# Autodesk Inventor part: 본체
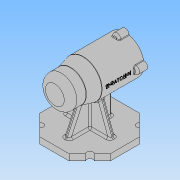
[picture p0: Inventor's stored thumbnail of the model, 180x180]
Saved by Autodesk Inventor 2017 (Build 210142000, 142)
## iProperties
Part Number: 본체
Material: 일반
Document SubType Name: Modeling
Designer: user
Density: 1 g/cm^3
Appearance: 기본값
Author: user
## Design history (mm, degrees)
sketch "스케치1"
  geometry: L1 (-56, 0)-(56, 0); L2 (-56, 0)-(-56, 25); L3 (-56, 25)-(-31, 25); L4 (-31, 25)-(-11, 30); L5 (-11, 30)-(56, 30); L6 (56, 30)-(56, 0); 2 further points
  constraints: 12 end point, 2 perpendicular, 1 coincident, 1 horizontal, 1 midpoint, 1 parallel, 1 vertical
  dimensions: "d0" = 112 distance of L1.start L1.end; "d1" = 25 distance of L2.end L3.end; "d2" = 45 distance from line of L4.end L2; "d3" = 50 diameter of L3 L1; "d4" = 60 diameter of L5 L1
revolve "회전1" sketch "스케치1" stored, may be unused: angle "d5" = 90 deg
sketch "스케치2"
  geometry: L1 (56, -30)-(56, 30) reference; L2 (-50, 0)-(56, 0); L3 (56, 0)-(56, 21); L4 (56, 21)-(41, 21); L5 (41, 21)-(41, 21); L6 (38, 24)-(-10, 24); L7 (-13, 21)-(-13, 21); L8 (-13, 21)-(-24.7, 21); L9 (-25, 20.7)-(-25, 17.5); L10 (-25, 17.5)-(-42.7, 17.5); L11 (-43, 17.2)-(-43, 16); L12 (-43, 16)-(-46.7, 16); L13 (-47, 15.7)-(-47, 10.5); L14 (-47, 10.5)-(-47, 10.5); L15 (-50, 7.5)-(-50, 0); A1 r 0.3 centre (-46.7, 15.7) between (-46.7, 16) and (-47, 15.7); A2 r 0.3 centre (-42.7, 17.2) between (-42.7, 17.5) and (-43, 17.2); A3 r 0.3 centre (-24.7, 20.7) between (-24.7, 21) and (-25, 20.7); A4 r 3 centre (-47, 7.5) between (-47, 10.5) and (-50, 7.5); A5 r 3 centre (-10, 21) between (-10, 24) and (-13, 21); A6 r 3 centre (38, 21) between (41, 21) and (38, 24); 7 further points
  constraints: 28 end point, 15 point on line, 12 point on circle, 12 tangent, 9 perpendicular, 6 centre point, 4 equal radius, 1 horizontal, 1 midpoint, 1 vertical
  dimensions: "d6" = 42 diameter of L4 L2; "d7" = 48 diameter of L6 L2; "d8" = 35 diameter of L10 L2; "d9" = 32 diameter of L12 L2; "d10" = 21 diameter of L14 L2; "d11" = 3 distance of L13.end point (-50, 10.5); "d12" = 4 distance of L11.end point (-47, 16); "d13" = 18 distance of L9.end point (-43, 17.5); "d14" = 54 distance of point (41, 24) point (-13, 24); "d15" = 15 distance of L3.end L4.end; "d16" = 12 distance of L7.end point (-25, 21); "d17" = 0.3 radius of A1; "d18" = 3 radius of A4
revolve "회전2" sketch "스케치2" stored, may be unused: angle "d19" = 90 deg
chamfer "모따기1" distance "d20" = 1; stored, may be unused: second distance "d21" = 2, angle "d22" = 45 deg
node "작업 평면1"
sketch "스케치3"
  geometry: L1 (-56, 30)-(-56, -30) reference; L2 (-23.196, -56.48)-(-56, -23.676); L3 (-56, -23.676)-(-56, 22.716); L4 (-56, 22.716)-(-23.196, 55.52); L5 (-23.196, 55.52)-(23.196, 55.52); L6 (23.196, 55.52)-(56, 22.716); L7 (56, 22.716)-(56, -23.676); L8 (56, -23.676)-(23.196, -56.48); L9 (23.196, -56.48)-(-23.196, -56.48); C1 r 56 at (0, -0.48); 2 further points
  constraints: 16 end point, 1 centre point, 1 coincident, 1 collinear, 1 tangent, 17 other
  dimensions: "d24" = 112 diameter of C1
extrude "돌출1" join sketch "스케치3" distance "d25" = 10; taper "d26" = 0 deg
sketch "스케치4"
  geometry: L1 (-56, 23.676)-(-56, -22.716) reference; L2 (56, -22.716)-(56, 23.676) reference; L3 (-38, -4)-(31, -4); L4 (31, -4)-(31, 4); L5 (31, 4)-(-38, 4); L6 (-38, 4)-(-38, -4); L7 (-38, -4)-(31, 4); L8 (31, -4)-(-38, 4); 3 further points
  constraints: 12 end point, 3 midpoint, 2 parallel, 1 horizontal, 1 horizontal alignment, 1 perpendicular
  dimensions: "d27" = 8 distance of L3.end L4.end; "d28" = 25 distance between parallel lines of L2 L4; "d29" = 18 distance between parallel lines of L1 L6
extrude "돌출2" join sketch "스케치4" stored distance "d30" = 10; taper "d31" = 0 deg
feature "면 기울기1" dims angle "d32" = 25 deg
sketch "스케치5"
  geometry: L1 (-70, -56.48)-(-80, -56.48) reference; L2 (-80, -56.48)-(-80, 55.52) reference; L3 (-80, 55.52)-(-70, 55.52) reference; L4 (-70, 55.52)-(-70, 4) reference; L5 (-70, 4)-(-29.732, 4) reference; L6 (-29.732, -4)-(-70, -4) reference; L7 (-70, -4)-(-70, -56.48) reference; L8 (-70, -36.48)-(-22.928, -19.347); C1 r 24 at (0, 0) reference; A1 r 30 centre (0, 0) between (-29.732, -4) and (-29.732, 4) reference; 1 further point
  constraints: 2 end point, 1 point on circle, 1 point on line
  dimensions: "d33" = 20 distance of L1.start L8.start; "d34" = 110 deg angle of L7 L8
feature "리브1" sketch "스케치5" dims "d35" = 1, "d36" = 8, "d37" = 0, "d38" = 0, "d39" = 1, "d40" = 1
sketch "스케치6"
  geometry: C1 r 6 at (0, 30); 1 further point
  constraints: 2 vertical alignment, 1 centre point, 1 other
  dimensions: "d41" = 12 diameter of C1
extrude "돌출3" join sketch "스케치6" distance "d42" = 16; taper "d43" = 0 deg
hole "구멍1" diameter "d49" = 3.242; stored, may be unused: countersink angle "d53" = 90 deg, drill point angle "d55" = 118 deg; dims "d47" = 10, "d48" = 10, "d50" = 8, "d51" = 4, "d52" = 2, "d54" = 11
sketch "스케치7"
  geometry: L1 (-56, 23.676)-(-56, -22.716) reference; L2 (56, -22.716)-(56, 23.676) reference; L3 (0, 0)-(-56, 0); L4 (0, 0)-(56, 0); C1 r 5 at (-39.598, 39.598); C2 r 5 at (39.598, 39.598); A1 r 56 centre (0, 0) between (-39.598, 39.598) and (-56, 0); 1 further point
  constraints: 4 end point, 4 point on circle, 3 centre point, 2 point on line, 1 coincident
  dimensions: "d59" = 112 diameter of A1; "d60" = 10 diameter of C1; "d61" = 45 deg dimension on point (0, 0) L3.end C1.centre; "d62" = 10 diameter of C2; "d63" = 45 deg dimension on point (0, 0) L4.end C2.centre
extrude "돌출4" cut sketch "스케치7" stored distance "d64" = 16; taper "d65" = 0 deg
fillet "모깎기1" dims "d66" = 10
fillet "모깎기2" dims "d67" = 3
fillet "모깎기3" dims "d68" = 1
fillet "모깎기4" dims "d69" = 3
fillet "모깎기5" dims "d70" = 3
fillet "모깎기6" dims "d71" = 3
node "작업 평면2"
sketch "스케치8"
  geometry: L1 (56, 6.771)-(56, 29.226) reference; L2 (-11, 30)-(39, 30) reference; 2 further points
  constraints: 1 other
  dimensions: "d73" = 41 distance from line of L1 point (15, 0); "d74" = 30 distance from line of L2 point (15, 0)
feature "엠보싱1" sketch "스케치8" dims "d6" = 42, "d7" = 48, "d8" = 35, "d9" = 32, "d10" = 21, "d11" = 3, "d12" = 4, "d13" = 18, "d14" = 54, "d15" = 15, "d16" = 12, "d17" = 0.3, "d18" = 3, "d75" = 0.5, "d76" = 0
fillet "모깎기7" dims "d77" = 3
node "솔리드1"
mirror "미러1"
pattern_circular "원형 패턴1" dims angle "d45" = 360 deg
pattern_circular "원형 패턴2" dims angle "d57" = 360 deg
mirror "미러2"
node "절단 모서리 투영1"
other parameters: "d72" = 39
